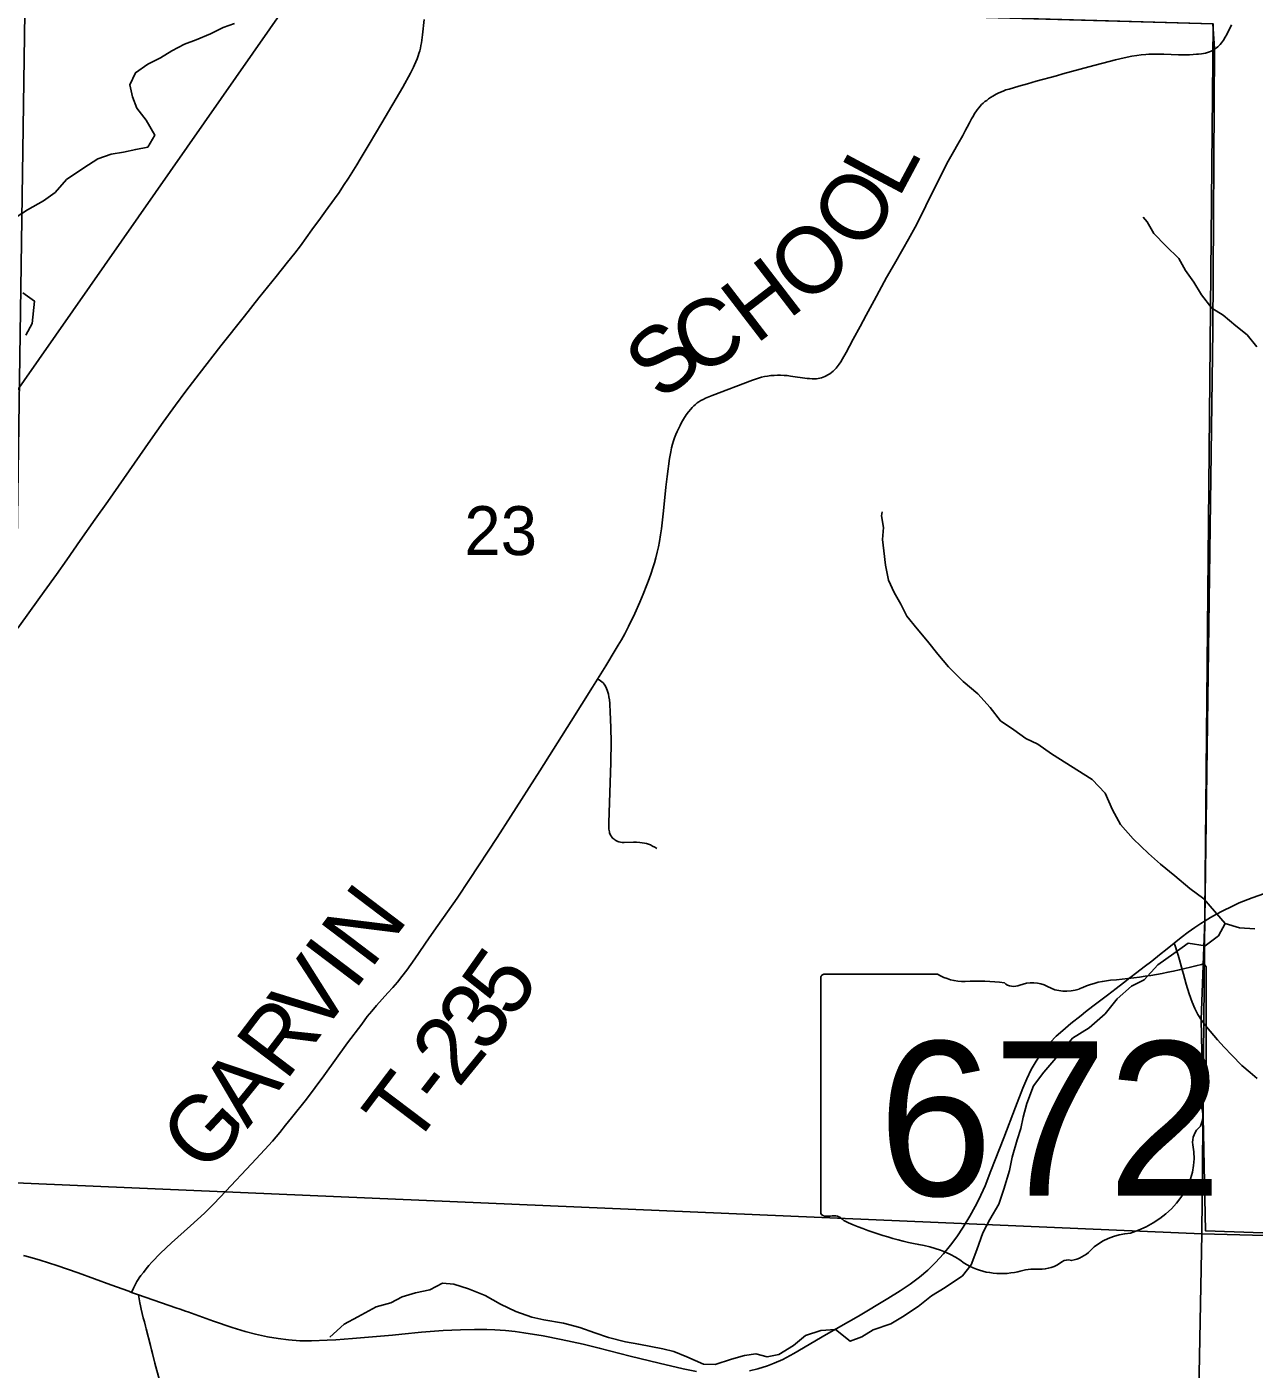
# Model space of a CAD drawing. Extents: x 0 to 34, y 0 to 22.
# Drawn here: x 25.06 to 26.11, y 16.564 to 17.712 of the extents above; entities that cross this region are included whole.
import ezdxf

# ---------------------------------------------------------------- set-up
doc = ezdxf.new("R2010")
doc.units = 0
for name, color, linetype in [('GM_X_Corporation', 7, 'Continuous'), ('GM_X_Minor_River', 7, 'Continuous'), ('GM_X_Rail_Line', 7, 'Continuous'), ('GM_X_Section_Text', 7, 'Continuous'), ('GM_X_State_Location', 7, 'Continuous'), ('GM_X_State_Route', 7, 'Continuous'), ('GM_X_State_Shield', 7, 'Continuous'), ('GM_X_Township_Road', 7, 'Continuous'), ('GM_X_Township_Road_Text', 7, 'Continuous')]:
    doc.layers.add(name, color=color, linetype=linetype)

msp = doc.modelspace()

# ---------------------------------------------------------------- linework, layer by layer
at = {"layer": 'GM_X_Corporation'}
for points in [[(30.3167, 20.9), (25.1014, 20.9), (25.0988, 20.7425), (25.0847, 19.8351), (25.0701, 18.7696), (25.0668, 18.5474), (25.0619, 17.7438), (25.4012, 17.7333), (26.0747, 17.7146), (26.0759, 17.6934), (26.0745, 17.4524), (26.0677, 16.948), (26.0646, 16.863), (26.0683, 16.6823), (26.3378, 16.673), (27.0694, 16.6556)], [(27.0694, 16.6556), (26.3378, 16.673), (26.0683, 16.6823), (26.0646, 16.863), (26.0677, 16.948), (26.0745, 17.4524), (26.0759, 17.6934), (26.0747, 17.7146)]]:
    msp.add_lwpolyline(points, dxfattribs=at)
for points in [[(26.075, 17.7146), (26.0652, 16.6798), (25.0442, 16.7237), (25.0591, 17.7438)], [(25.0442, 16.7237), (26.0652, 16.6798), (26.0458, 15.6621), (25.0261, 15.6992)], [(26.0652, 16.6798), (27.0742, 16.6531), (27.0738, 16.6357), (27.0577, 15.6306), (26.0458, 15.6621)]]:
    msp.add_lwpolyline(points, close=True, dxfattribs=at)
at = {"layer": 'GM_X_Minor_River'}
for points in [[(25.0513, 17.5492), (25.0611, 17.5554), (25.0746, 17.5631), (25.0847, 17.5704), (25.0945, 17.5815), (25.1091, 17.5915), (25.1212, 17.5992), (25.1325, 17.6031), (25.143, 17.6047), (25.1536, 17.6071), (25.1638, 17.6091), (25.1698, 17.6194), (25.1625, 17.6322), (25.1544, 17.6424), (25.1509, 17.6522), (25.1486, 17.6624), (25.1534, 17.6727), (25.1639, 17.68), (25.1749, 17.6854), (25.1846, 17.6916), (25.1952, 17.6973), (25.2053, 17.7009), (25.2174, 17.7059), (25.2283, 17.7113), (25.2381, 17.7148)], [(26.1122, 17.4383), (26.1038, 17.4485), (26.0943, 17.4563), (26.0833, 17.4653), (26.0738, 17.4713), (26.065, 17.4829), (26.0584, 17.4935), (26.0512, 17.5036), (26.0454, 17.5138), (26.0344, 17.5247), (26.0241, 17.5352), (26.0183, 17.5453), (26.0149, 17.5491)], [(25.0597, 17.4482), (25.0649, 17.4584), (25.067, 17.4774), (25.0571, 17.4845)], [(25.9715, 17.0684), (25.9365, 17.0902), (25.925, 17.0984), (25.9148, 17.1033), (25.9045, 17.1107), (25.8931, 17.1186), (25.8843, 17.1298), (25.8736, 17.1415), (25.8611, 17.152), (25.8485, 17.1647), (25.8393, 17.1756), (25.8305, 17.1865), (25.8217, 17.197), (25.8129, 17.2079), (25.8079, 17.2181), (25.8022, 17.2282), (25.7972, 17.2388), (25.7948, 17.2517), (25.7932, 17.2638), (25.792, 17.2736), (25.793, 17.2838), (25.7914, 17.2937), (25.7918, 17.2971)], [(26.085, 16.9452), (26.067, 16.9663), (26.0548, 16.975), (26.0422, 16.9859), (26.0297, 16.996), (26.0197, 17.005), (26.0064, 17.0175), (25.9957, 17.0299), (25.9888, 17.0424), (25.9826, 17.0567), (25.9715, 17.0684)], [(26.1104, 16.9405), (26.0975, 16.9415), (26.085, 16.9452), (26.0794, 16.9346), (26.0681, 16.9261), (26.0536, 16.9283), (26.0412, 16.9195), (26.0276, 16.9099), (26.016, 16.8969), (26.005, 16.8915), (25.9929, 16.8807), (25.9824, 16.8678), (25.9689, 16.8559), (25.9545, 16.847), (25.9402, 16.8299), (25.9301, 16.818), (25.9211, 16.8062), (25.9155, 16.7913), (25.9125, 16.7795), (25.9103, 16.7697)], [(25.9103, 16.7697), (25.9074, 16.7601), (25.9029, 16.7453), (25.9007, 16.7339), (25.8959, 16.7179), (25.8915, 16.705), (25.884, 16.692), (25.878, 16.6806), (25.8728, 16.6661), (25.868, 16.6532), (25.8604, 16.6437), (25.8457, 16.6337), (25.834, 16.6267), (25.8227, 16.6175), (25.8091, 16.6087), (25.7993, 16.6029), (25.7842, 16.5975), (25.7744, 16.5917), (25.7646, 16.5879), (25.752, 16.598), (25.7395, 16.5971), (25.7262, 16.5929), (25.7161, 16.5841), (25.7036, 16.5764), (25.6934, 16.5744), (25.6839, 16.577), (25.674, 16.5758), (25.6631, 16.5726), (25.6491, 16.568), (25.6392, 16.5683), (25.6248, 16.5746), (25.6137, 16.5791), (25.6042, 16.5813), (25.594, 16.5835), (25.5837, 16.5853), (25.5723, 16.5875), (25.5579, 16.5911), (25.5461, 16.5952), (25.5332, 16.5997), (25.5195, 16.6034), (25.5025, 16.6062), (25.4922, 16.6084), (25.4785, 16.6133), (25.4656, 16.6196), (25.4523, 16.6271), (25.4382, 16.6327), (25.4257, 16.6367), (25.4158, 16.6374), (25.4052, 16.6317), (25.3927, 16.6293), (25.3814, 16.6258), (25.3716, 16.6208), (25.3591, 16.6172), (25.3436, 16.6088), (25.3319, 16.6026), (25.3195, 16.5915)]]:
    msp.add_lwpolyline(points, dxfattribs=at)
at = {"layer": 'GM_X_Rail_Line'}
msp.add_lwpolyline([(27.3181, 19.0787), (26.8719, 18.963), (26.6364, 18.9022), (26.5984, 18.8925), (26.5599, 18.88), (26.5181, 18.863), (26.4939, 18.8489), (26.4659, 18.8316), (26.3299, 18.7221), (25.6255, 18.1395), (25.5717, 18.0909), (25.5316, 18.0529), (25.4885, 18.0044), (25.4477, 17.9591), (25.4146, 17.9181), (25.3806, 17.8712), (24.8603, 17.1266), (24.3577, 16.4125), (24.3204, 16.3658), (24.2794, 16.3248), (24.2417, 16.292), (23.9897, 16.0983), (23.6678, 15.8432), (23.5167, 15.7235)], dxfattribs=at)
at = {"layer": 'GM_X_State_Route'}
msp.add_line((25.1501, 16.6297), (25.1561, 16.6276), dxfattribs=at)
for points in [[(25.0529, 17.1976), (25.0637, 17.2128), (25.0752, 17.229), (25.0859, 17.2435), (25.0948, 17.2562), (25.1061, 17.2726), (25.1189, 17.2909), (25.1297, 17.3061), (25.1663, 17.3586), (25.1771, 17.3738), (25.1876, 17.3884), (25.1963, 17.4005), (25.2078, 17.4152), (25.2265, 17.4392), (25.2465, 17.4646), (25.2589, 17.4801), (25.2736, 17.4986), (25.2834, 17.5106), (25.2895, 17.5184), (25.2944, 17.5248), (25.3042, 17.5383), (25.3116, 17.5483), (25.3159, 17.5544), (25.3236, 17.5649), (25.3274, 17.5703), (25.3313, 17.5762), (25.3354, 17.5825), (25.3397, 17.5893), (25.3427, 17.594), (25.3456, 17.5988), (25.3533, 17.6116), (25.3639, 17.6298), (25.3819, 17.6603), (25.3884, 17.6723), (25.391, 17.6775), (25.3919, 17.6795), (25.3931, 17.6821), (25.3942, 17.6846), (25.3951, 17.6871), (25.3958, 17.6892), (25.3965, 17.6915), (25.397, 17.6938), (25.3975, 17.696), (25.3979, 17.6983), (25.3983, 17.7005), (25.3989, 17.7052), (25.4003, 17.7182)], [(26.0679, 16.9475), (26.0727, 16.9504), (26.0776, 16.9531), (26.0826, 16.9557), (26.0915, 16.9601), (26.0972, 16.9627), (26.1082, 16.9671), (26.1187, 16.9709)], [(25.6785, 16.5625), (25.6856, 16.5643), (25.6939, 16.5669), (25.6996, 16.5692), (25.7069, 16.5724), (25.7162, 16.5774), (25.7441, 16.5936), (25.7716, 16.6094), (25.7967, 16.6243), (25.8072, 16.6309), (25.8159, 16.6368), (25.8238, 16.6428), (25.8308, 16.6488), (25.8375, 16.6552), (25.8442, 16.6625), (25.8504, 16.6701), (25.8556, 16.6771), (25.8611, 16.6853), (25.8669, 16.6948), (25.8714, 16.703), (25.8744, 16.709), (25.8798, 16.7209), (25.8849, 16.7335), (25.896, 16.7619), (25.9059, 16.788), (25.9121, 16.8043), (25.9155, 16.8123), (25.9193, 16.8202), (25.9234, 16.8273), (25.9271, 16.833), (25.9309, 16.838), (25.9354, 16.8433), (25.9406, 16.8487), (25.9462, 16.8537), (25.9533, 16.8597), (25.9621, 16.8665), (25.9658, 16.8695), (25.9721, 16.8744), (25.9844, 16.8839), (25.9918, 16.8895), (25.9981, 16.8945), (26.0036, 16.8986), (26.0095, 16.9032), (26.0159, 16.908), (26.0223, 16.913), (26.0291, 16.9184), (26.0354, 16.9235), (26.0414, 16.9282), (26.0476, 16.9331), (26.0535, 16.9376), (26.0591, 16.9416), (26.0642, 16.9451), (26.0679, 16.9475)], [(25.0575, 16.6612), (25.063, 16.6598), (25.0719, 16.6572), (25.0862, 16.6527), (25.1044, 16.6464), (25.1324, 16.6361), (25.1476, 16.6306), (25.1501, 16.6297)], [(25.1561, 16.6276), (25.188, 16.6164), (25.1915, 16.6152), (25.1962, 16.6136), (25.198, 16.6131), (25.2044, 16.6107), (25.2202, 16.6051), (25.236, 16.5997), (25.2472, 16.5962), (25.2561, 16.5939), (25.2664, 16.5916), (25.2755, 16.5901), (25.2841, 16.589), (25.2939, 16.5883), (25.3038, 16.5882), (25.3174, 16.5888), (25.3248, 16.5892), (25.339, 16.5902), (25.3731, 16.5931), (25.3811, 16.5939), (25.3978, 16.5955), (25.4164, 16.597), (25.4313, 16.5976), (25.4432, 16.5979), (25.4538, 16.5979), (25.4606, 16.5977), (25.4699, 16.5971), (25.478, 16.5963), (25.4854, 16.5952), (25.502, 16.5925), (25.5173, 16.5895), (25.5361, 16.5854), (25.55, 16.582), (25.5765, 16.5752), (25.6012, 16.5692), (25.6217, 16.5644), (25.6332, 16.5621)]]:
    msp.add_lwpolyline(points, dxfattribs=at)
at = {"layer": 'GM_X_State_Shield'}
for p, q in [((25.7394, 16.8984), (25.7394, 16.6983)), ((25.8392, 16.9019), (25.7426, 16.9019)), ((26.069, 16.8021), (26.069, 16.9068)), ((26.0689, 16.8022), (26.069, 16.8021))]:
    msp.add_line(p, q, dxfattribs=at)
for centre, major_axis, start_param, end_param in [((25.9516, 17.1747), (0.3495, 0), 4.814394, 5.042369), ((26.0653, 16.9073), (0.00367, 0), 6.141152, 7.989035), ((25.7432, 16.8989), (0.00382, 0), 1.712693, 3.28349), ((25.8621, 16.9251), (0.037, 0), 4.042523, 4.731795), ((25.8744, 16.7895), (0.133, 0), 1.404758, 1.657858), ((25.9046, 16.8999), (0.0107, 0), 3.836095, 5.185415), ((25.9203, 16.8768), (0.0222, 0), 0.950623, 2.079405), ((25.949, 16.9085), (0.0267, 0), 4.081561, 5.145723), ((25.9962, 16.8408), (0.0703, 0), 1.699011, 2.107814), ((26.0681, 16.7945), (0.00568, 0), 1.883978, 3.671073), ((26.0651, 16.8017), (0.00393, 0), 5.05454, 6.418171), ((26.032, 16.7812), (0.0341, 0), 5.934695, 6.695948), ((26.0821, 16.7583), (0.0248, 0), 2.387724, 3.262537), ((25.9711, 16.745), (0.0874, 0), 5.101752, 6.440018), ((25.7432, 16.6979), (0.00385, 0), 3.00124, 4.508301), ((25.7438, 16.7183), (0.0294, 0), 4.665946, 4.897461), ((25.7498, 16.6868), (0.0106, 0), 0.519207, 1.627899), ((25.8836, 16.8666), (0.2524, 0), 4.195997, 4.488961), ((26.008, 16.6421), (0.0479, 0), 1.647645, 2.488434), ((25.8084, 16.6084), (0.079, 0), 0.823519, 1.323587), ((25.9506, 16.6514), (0.00752, 0), 1.147584, 2.315152), ((25.9473, 16.6789), (0.0282, 0), 4.937069, 5.64225), ((25.8938, 16.6858), (0.0501, 0), 4.026481, 4.996735), ((25.9227, 16.6166), (0.0412, 0), 1.495662, 1.94098), ((25.9264, 16.6708), (0.0267, 0), 4.691044, 5.507374)]:
    msp.add_ellipse(centre, major_axis=major_axis, ratio=0.8, start_param=start_param, end_param=end_param, dxfattribs=at)
at = {"layer": 'GM_X_Township_Road'}
msp.add_line((25.1561, 16.6276), (25.1501, 16.6297), dxfattribs=at)
for points in [[(26.0754, 17.6925), (26.0761, 17.6929), (26.0777, 17.6941), (26.0789, 17.695), (26.08, 17.696), (26.0809, 17.697), (26.082, 17.6983), (26.0829, 17.6994), (26.0837, 17.7007), (26.0852, 17.7031), (26.0865, 17.7054), (26.0906, 17.7138)], [(25.5485, 17.154), (25.5555, 17.1654), (25.5634, 17.1788), (25.5661, 17.1831), (25.5689, 17.1878), (25.5717, 17.1929), (25.575, 17.1992), (25.5804, 17.2103), (25.5847, 17.22), (25.5876, 17.2269), (25.5907, 17.2349), (25.5926, 17.2399), (25.5943, 17.2448), (25.5958, 17.2492), (25.5971, 17.2536), (25.5983, 17.258), (25.5995, 17.2626), (25.6005, 17.2674), (25.6014, 17.2717), (25.6023, 17.2776), (25.6031, 17.2827), (25.6049, 17.2981), (25.607, 17.3184), (25.608, 17.3274), (25.61, 17.3428), (25.611, 17.3485), (25.6118, 17.3519), (25.6127, 17.3552), (25.6135, 17.3579), (25.6144, 17.3605), (25.6154, 17.3632), (25.6166, 17.3658), (25.6177, 17.3683), (25.619, 17.3709), (25.6204, 17.3736), (25.622, 17.3764), (25.6243, 17.3801), (25.6262, 17.3826), (25.6282, 17.3851), (25.6294, 17.3865), (25.6307, 17.3879), (25.6322, 17.3891), (25.6337, 17.3903), (25.6352, 17.3914), (25.6369, 17.3924), (25.6387, 17.3934), (25.6408, 17.3944), (25.6436, 17.3956), (25.6466, 17.3968), (25.6809, 17.4099), (25.6834, 17.4107), (25.6862, 17.4116), (25.6887, 17.4123), (25.6911, 17.4128), (25.6939, 17.4133), (25.6967, 17.4137), (25.6995, 17.4139), (25.7024, 17.414), (25.705, 17.414), (25.708, 17.4139), (25.7107, 17.4137), (25.7136, 17.4133), (25.7277, 17.4113), (25.7297, 17.4111), (25.732, 17.411), (25.7338, 17.4109), (25.7356, 17.411), (25.737, 17.4112), (25.7385, 17.4115), (25.7399, 17.4118), (25.7414, 17.4123), (25.7427, 17.4128), (25.744, 17.4135), (25.7455, 17.4143), (25.7471, 17.4153), (25.7485, 17.4164), (25.7499, 17.4175), (25.7524, 17.4201), (25.755, 17.4234), (25.7566, 17.4256), (25.758, 17.428), (25.7611, 17.4334), (25.764, 17.4389), (25.7671, 17.4448), (25.773, 17.4558), (25.7783, 17.4655), (25.7851, 17.478), (25.7956, 17.4976), (25.8023, 17.5094), (25.8095, 17.5218), (25.8143, 17.5304), (25.82, 17.5406), (25.8262, 17.553), (25.8321, 17.565), (25.8375, 17.5755), (25.8415, 17.5838), (25.8484, 17.597), (25.8527, 17.6052), (25.8565, 17.6117), (25.8608, 17.6191), (25.8631, 17.6235), (25.8645, 17.6262), (25.8665, 17.63), (25.8682, 17.6332), (25.8698, 17.636), (25.8708, 17.6378), (25.8718, 17.6394), (25.873, 17.641), (25.8745, 17.6428), (25.8756, 17.6442), (25.8769, 17.6455), (25.8782, 17.6467), (25.8797, 17.648), (25.8812, 17.6491), (25.8827, 17.6503), (25.8845, 17.6515), (25.8864, 17.6528), (25.8878, 17.6536), (25.8894, 17.6545), (25.8909, 17.6552), (25.893, 17.6562), (25.8952, 17.6571), (25.8976, 17.658), (25.9003, 17.6588), (25.9087, 17.6612), (25.9162, 17.6632), (25.9236, 17.6654), (25.941, 17.6702), (25.9464, 17.6717), (25.9685, 17.6779), (25.9914, 17.6837), (25.9987, 17.6854), (26.0054, 17.6868), (26.0097, 17.6876), (26.0133, 17.688), (26.0172, 17.6883), (26.0199, 17.6885), (26.0228, 17.6886), (26.0328, 17.6885), (26.0452, 17.688), (26.0514, 17.688), (26.0546, 17.6881), (26.0577, 17.6883), (26.0605, 17.6885), (26.0624, 17.6887), (26.0649, 17.689), (26.0666, 17.6893), (26.0683, 17.6896), (26.07, 17.69), (26.0716, 17.6905), (26.0732, 17.6912), (26.0748, 17.6921), (26.0754, 17.6925)], [(25.1501, 16.6297), (25.1518, 16.6333), (25.1537, 16.6372), (25.1546, 16.639), (25.1556, 16.6406), (25.1566, 16.6422), (25.1579, 16.644), (25.1601, 16.6468), (25.1624, 16.6497), (25.1648, 16.6526), (25.1673, 16.6554), (25.1747, 16.6631), (25.1842, 16.672), (25.2004, 16.6865), (25.2123, 16.6974), (25.2203, 16.7053), (25.2305, 16.7161), (25.2527, 16.7395), (25.264, 16.7519), (25.2704, 16.7591), (25.2767, 16.7664), (25.2817, 16.7726), (25.2869, 16.7789), (25.2996, 16.7949), (25.3144, 16.8149), (25.3348, 16.8431), (25.3468, 16.859), (25.3516, 16.8655), (25.3555, 16.8703), (25.3595, 16.8751), (25.3691, 16.8857), (25.3733, 16.8903), (25.3773, 16.8951), (25.3812, 16.8998), (25.3853, 16.9053), (25.3921, 16.9149), (25.4044, 16.9328), (25.4119, 16.9435), (25.4283, 16.9669), (25.439, 16.9829), (25.4626, 17.0187), (25.4743, 17.037), (25.4992, 17.0757), (25.5258, 17.1183), (25.5442, 17.1473), (25.5485, 17.154)], [(25.5485, 17.154), (25.5498, 17.1534), (25.551, 17.1528), (25.5522, 17.1519), (25.5532, 17.151), (25.5541, 17.1499), (25.5548, 17.1489), (25.5555, 17.1476), (25.5562, 17.1461), (25.5568, 17.1447), (25.5573, 17.1431), (25.5577, 17.1413), (25.5582, 17.1391), (25.5586, 17.1365), (25.5589, 17.1334), (25.5594, 17.1254), (25.5596, 17.1204), (25.5599, 17.1117), (25.56, 17.1011), (25.5597, 17.0824), (25.5581, 17.0315), (25.5581, 17.0284), (25.5582, 17.0259), (25.5584, 17.0246), (25.5586, 17.0236), (25.5588, 17.0225), (25.5592, 17.0216), (25.5596, 17.0208), (25.5601, 17.0199), (25.5606, 17.0192), (25.5611, 17.0185), (25.5618, 17.0178), (25.5626, 17.0172), (25.5633, 17.0166), (25.564, 17.0161), (25.5648, 17.0157), (25.5657, 17.0153), (25.5668, 17.0149), (25.5681, 17.0147), (25.5695, 17.0145), (25.5712, 17.0145), (25.5793, 17.0147), (25.5819, 17.0147), (25.5845, 17.0145), (25.5866, 17.0142), (25.5885, 17.0139), (25.5903, 17.0135), (25.592, 17.013), (25.5937, 17.0123), (25.5956, 17.0114), (25.5975, 17.0104), (25.5993, 17.0092)], [(26.0648, 16.8625), (26.0617, 16.8674), (26.0592, 16.8723), (26.0568, 16.878), (26.0543, 16.885), (26.0517, 16.8933), (26.0495, 16.9017), (26.0486, 16.9047), (26.046, 16.9142), (26.0448, 16.9181), (26.0437, 16.9216), (26.0426, 16.9251), (26.0414, 16.9282)], [(26.1125, 16.8125), (26.1064, 16.8176), (26.0995, 16.8238), (26.0908, 16.8326), (26.0844, 16.8393), (26.0787, 16.8457), (26.0691, 16.8569), (26.0648, 16.8625)], [(25.1739, 16.5546), (25.1699, 16.569), (25.1678, 16.5774), (25.167, 16.5804), (25.1662, 16.5841), (25.1625, 16.5984), (25.1619, 16.6008), (25.161, 16.6044), (25.16, 16.608), (25.159, 16.6116), (25.1582, 16.6152), (25.1577, 16.6182), (25.1571, 16.6207), (25.1561, 16.6276)]]:
    msp.add_lwpolyline(points, dxfattribs=at)

# ---------------------------------------------------------------- texts
at = {"layer": 'GM_X_Section_Text'}
msp.add_text('23', height=0.04186, rotation=0, dxfattribs=at).set_placement((25.4345, 17.2602))
at = {"layer": 'GM_X_State_Location'}
for s in ['s', 'r']:
    msp.add_text(s, height=0.000189, dxfattribs=at).set_placement((25.9005, 16.7851))
msp.add_text('672', height=0.000189, rotation=0, dxfattribs=at).set_placement((25.8336, 16.7713))
at = {"layer": 'GM_X_State_Shield'}
msp.add_text('672', height=0.13184, dxfattribs=at).set_placement((25.7884, 16.7124))
at = {"layer": 'GM_X_Township_Road_Text'}
for s, rotation, p in [('L', 61.8733, (25.8058, 17.5642)), ('O', 56.8884, (25.7758, 17.5177)), ('O', 40.1559, (25.7256, 17.472)), ('H', 37.5198, (25.6837, 17.4397)), ('C', 24.201, (25.6288, 17.4132)), ('S', 40.9834, (25.6036, 17.3904)), ('N', 52.8303, (25.3543, 16.9051)), ('V', 52.8322, (25.31, 16.8467)), ('I', 52.8361, (25.3402, 16.8865)), ('5', 54.8135, (25.4754, 16.862)), ('3', 52.7506, (25.4529, 16.8324)), ('R', 52.7851, (25.2818, 16.8095)), ('2', 50.7315, (25.4294, 16.8036)), ('A', 50.9788, (25.2491, 16.7691)), ('T', 52.9192, (25.3899, 16.7516)), ('-', 52.3448, (25.4154, 16.7854)), ('G', 46.8047, (25.2119, 16.7292))]:
    msp.add_text(s, height=0.0568, rotation=rotation, dxfattribs=at).set_placement(p)

doc.saveas('drawing.dxf')
